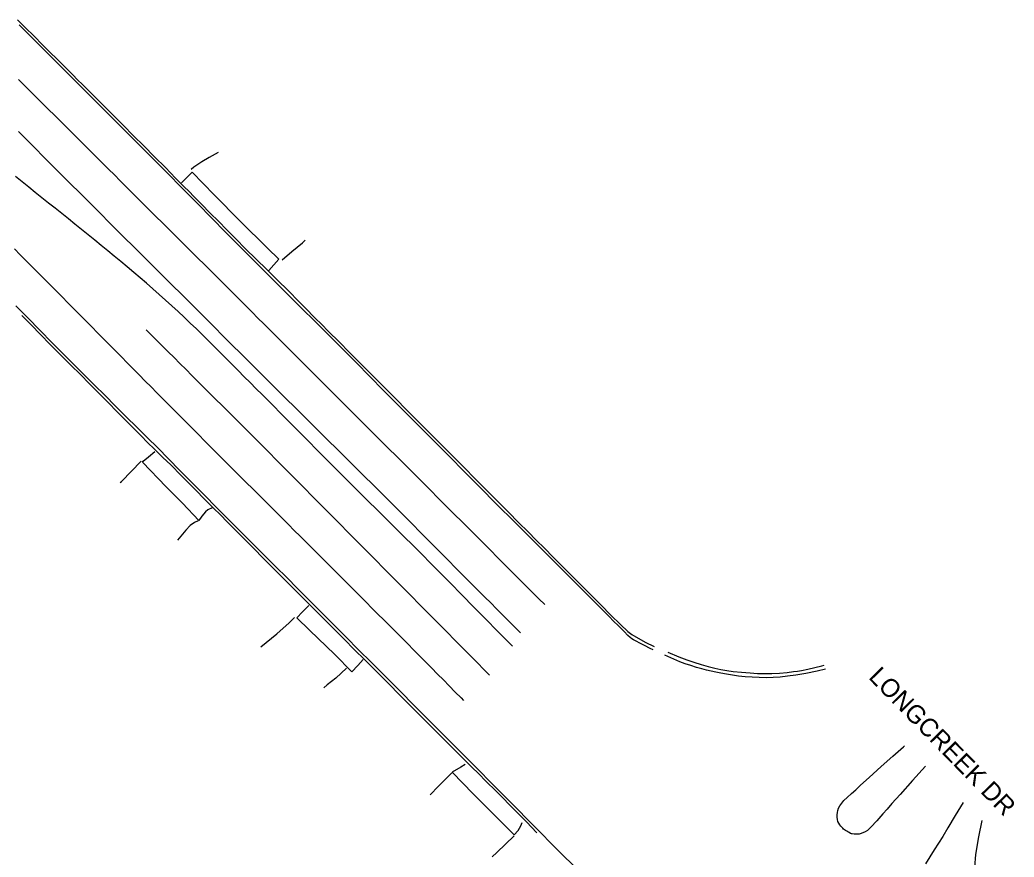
# Model space of a CAD drawing. Extents: x 1970211 to 1973046, y 801032 to 804001.
# Drawn here: x 1972255 to 1972549.2, y 801847.3 to 802095.2 of the extents above; entities that cross this region are included whole.
import ezdxf

# ---------------------------------------------------------------- set-up
doc = ezdxf.new("R2010")
doc.units = 0
for name, color, linetype in [('RD_EX_Conc', 7, 'Continuous'), ('RD_EX_Road', 7, 'Continuous'), ('RD_EX_Road_Paint', 7, 'Continuous'), ('RD_TX_RoadID', 7, 'Continuous')]:
    doc.layers.add(name, color=color, linetype=linetype)

msp = doc.modelspace()

# ---------------------------------------------------------------- linework, layer by layer
at = {"layer": 'RD_EX_Conc'}
for points in [[(1972254.32, 802095.16), (1972256.6, 802092.88), (1972259.19, 802090.31), (1972261.74, 802087.79), (1972263.9, 802085.63), (1972266.02, 802083.5), (1972268.46, 802081.06), (1972270.66, 802078.85), (1972272.09, 802077.43), (1972273.54, 802076), (1972275.78, 802073.77), (1972278.68, 802070.88), (1972282.09, 802067.46), (1972285.56, 802063.97), (1972288.64, 802060.87), (1972291.64, 802057.86), (1972294.86, 802054.65), (1972298.08, 802051.41), (1972301.09, 802048.34), (1972303.53, 802045.84), (1972305.04, 802044.31), (1972306.48, 802042.86), (1972308.73, 802040.59), (1972311.31, 802037.98), (1972313.75, 802035.52), (1972316.22, 802033.02), (1972318.9, 802030.31), (1972321.8, 802027.41), (1972324.92, 802024.35), (1972328.11, 802021.23), (1972331.23, 802018.14), (1972334.37, 802015), (1972337.63, 802011.72), (1972340.26, 802009.05), (1972341.52, 802007.76), (1972342.46, 802006.8), (1972344.12, 802005.13), (1972346.43, 802002.82), (1972349.33, 801999.92), (1972352.66, 801996.57), (1972356.27, 801992.94), (1972359.79, 801989.4), (1972362.87, 801986.3), (1972365.99, 801983.17), (1972369.6, 801979.51), (1972373.26, 801975.82), (1972376.51, 801972.57), (1972379.65, 801969.43), (1972383.01, 801966.07), (1972386.42, 801962.63), (1972389.74, 801959.28), (1972393.02, 801955.97), (1972396.31, 801952.67), (1972399.52, 801949.45), (1972402.57, 801946.38), (1972405.36, 801943.56), (1972407.8, 801941.11), (1972410.17, 801938.73), (1972412.77, 801936.14), (1972415.55, 801933.37), (1972418.45, 801930.46), (1972421.34, 801927.55), (1972424.08, 801924.78), (1972426.85, 801921.95), (1972429.87, 801918.91), (1972432.69, 801916.13), (1972434.85, 801914.12), (1972436.03, 801913.23), (1972439.99, 801910.96), (1972442.69, 801909.63)], [(1972302.78, 802046.9), (1972304.18, 802048.29), (1972305.95, 802050.06), (1972312.46, 802043.38), (1972320.22, 802035.57), (1972328.25, 802027.61), (1972331.62, 802024.32), (1972330.13, 802022.65), (1972328.69, 802020.93)], [(1972407.96, 801854.5), (1972404.88, 801857.7), (1972402.22, 801860.41), (1972399.91, 801862.74), (1972397.88, 801864.81), (1972395.74, 801866.99), (1972393.1, 801869.63), (1972390.59, 801872.12), (1972388.85, 801873.84), (1972387.03, 801875.64), (1972384.25, 801878.41), (1972381.02, 801881.63), (1972377.83, 801884.81), (1972374.62, 801888.03), (1972371.29, 801891.37), (1972367.7, 801894.98), (1972363.72, 801899.02), (1972359.93, 801902.84), (1972356.93, 801905.81), (1972354.09, 801908.61), (1972350.8, 801911.9), (1972347.39, 801915.33), (1972344.22, 801918.51), (1972341.37, 801921.38), (1972338.92, 801923.85), (1972336.57, 801926.23), (1972333.99, 801928.81), (1972331.01, 801931.79), (1972327.48, 801935.33), (1972323.68, 801939.16), (1972319.89, 801942.97), (1972316.55, 801946.33), (1972314.11, 801948.78), (1972312.47, 801950.44), (1972311.52, 801951.38), (1972310, 801952.92), (1972306.63, 801956.35), (1972302.73, 801960.3), (1972299.62, 801963.39), (1972297.34, 801965.62), (1972295.96, 801966.96), (1972294.72, 801968.15), (1972292.89, 801969.97), (1972290.75, 801972.12), (1972288.58, 801974.3), (1972286.29, 801976.62), (1972283.78, 801979.15), (1972281.12, 801981.84), (1972278.35, 801984.63), (1972275.58, 801987.43), (1972272.89, 801990.13), (1972270.11, 801992.91), (1972267.04, 801995.99), (1972263.96, 801999.1), (1972261.11, 802001.99), (1972258.33, 802004.83), (1972255.58, 802007.64)], [(1972311.92, 801950.74), (1972310.6, 801950.15), (1972309.94, 801949.49), (1972308.86, 801948.21), (1972307.98, 801946.95), (1972303.1, 801952.04), (1972298.28, 801956.95), (1972291.3, 801964.26), (1972291.47, 801964.47), (1972293.08, 801965.78), (1972294.91, 801967.37)], [(1972284.69, 801958.16), (1972285.05, 801958.52), (1972290.9, 801964.47)], [(1972307.75, 801946.81), (1972306.66, 801946.33), (1972305.37, 801945.43), (1972304.08, 801944.05), (1972302.15, 801941.76), (1972301.61, 801941.11)], [(1972340.52, 801921.81), (1972338.62, 801919.95), (1972336.93, 801918.13), (1972340.71, 801914.52), (1972348.19, 801907.27), (1972353.23, 801902.2), (1972354.95, 801904.04), (1972356.61, 801905.76)], [(1972446.68, 801907.93), (1972449.97, 801906.62), (1972452.36, 801905.73), (1972454.37, 801905.05), (1972456.54, 801904.36), (1972458.68, 801903.73), (1972460.61, 801903.25), (1972462.4, 801902.86), (1972464.12, 801902.53), (1972466.06, 801902.25), (1972468.53, 801902.01), (1972471.06, 801901.82), (1972473.21, 801901.68), (1972475.24, 801901.62), (1972477.44, 801901.65), (1972479.72, 801901.77), (1972481.97, 801901.99), (1972483.88, 801902.22), (1972485.1, 801902.37), (1972486.3, 801902.57), (1972488.14, 801902.96), (1972490.24, 801903.45), (1972492.25, 801903.94), (1972492.99, 801904.14)], [(1972522.93, 801874.23), (1972519.08, 801869.96), (1972515.41, 801865.86), (1972512.99, 801863.14), (1972511.57, 801861.53), (1972510.34, 801860.13), (1972508.51, 801858.06), (1972506.76, 801856.14), (1972505.77, 801855.2), (1972505.12, 801854.79), (1972504.4, 801854.45), (1972503.65, 801854.21), (1972503.27, 801854.14), (1972502.54, 801854.09), (1972501.87, 801854.11), (1972501.28, 801854.18), (1972501.01, 801854.24), (1972500.76, 801854.33), (1972500.31, 801854.55), (1972499.93, 801854.75), (1972499.62, 801854.95), (1972499.31, 801855.14), (1972499.01, 801855.36), (1972498.73, 801855.61), (1972498.47, 801855.89), (1972498.2, 801856.18), (1972497.91, 801856.49), (1972497.6, 801856.86), (1972497.29, 801857.31), (1972497.04, 801857.84), (1972496.87, 801858.44), (1972496.79, 801859.11), (1972496.81, 801859.83), (1972496.87, 801860.5), (1972496.99, 801861.12), (1972497.24, 801861.79), (1972497.63, 801862.52), (1972498.15, 801863.26), (1972498.82, 801864.02), (1972499.78, 801864.96), (1972501.01, 801866.09), (1972502.3, 801867.25), (1972503.75, 801868.56), (1972506.29, 801870.89), (1972509.87, 801874.17), (1972513.24, 801877.2), (1972516.4, 801879.95), (1972516.7, 801880.21)], [(1972386.7, 801874.68), (1972385.44, 801873.88), (1972382.93, 801872.47), (1972389.13, 801866.07), (1972395.53, 801859.62), (1972401.21, 801853.87), (1972402.41, 801855.22), (1972403.26, 801856.58), (1972403.65, 801857.5)], [(1972534.13, 801863.47), (1972531.74, 801859.58), (1972529.54, 801855.94), (1972528.04, 801853.44), (1972526.83, 801851.47), (1972525.53, 801849.43), (1972524.2, 801847.35), (1972522.9, 801845.28)], [(1972537.5, 801844.34), (1972537.81, 801848.1), (1972538.69, 801853.33), (1972539.71, 801858.11)]]:
    msp.add_lwpolyline(points, dxfattribs=at)
at = {"layer": 'RD_EX_Road'}
for points in [[(1972442.36, 801908.62), (1972441.44, 801909.09), (1972439.8, 801909.92), (1972438.38, 801910.64), (1972437.34, 801911.19), (1972436.59, 801911.61), (1972436.1, 801911.93), (1972435.58, 801912.34), (1972434.92, 801912.93), (1972433.74, 801914.08), (1972432.08, 801915.75), (1972430.68, 801917.16), (1972429.33, 801918.52), (1972426.12, 801921.74), (1972421.05, 801926.82), (1972416.04, 801931.85), (1972411.33, 801936.57), (1972406.44, 801941.46), (1972401.33, 801946.55), (1972396.15, 801951.73), (1972391.01, 801956.9), (1972386.38, 801961.56), (1972382.29, 801965.67), (1972378.56, 801969.45), (1972375.04, 801973.01), (1972371.21, 801976.86), (1972367.02, 801981.04), (1972362.73, 801985.35), (1972358.46, 801989.67), (1972354.58, 801993.59), (1972351.03, 801997.15), (1972347.07, 802001.11), (1972342.63, 802005.54), (1972338.03, 802010.13), (1972333.41, 802014.76), (1972329.28, 802018.88), (1972325.55, 802022.58), (1972321.14, 802027.01), (1972316.08, 802032.14), (1972311.61, 802036.68), (1972307.75, 802040.6), (1972303.31, 802045.08), (1972298.25, 802050.17), (1972293.45, 802054.99), (1972289.01, 802059.45), (1972284.66, 802063.79), (1972280.29, 802068.15), (1972275.53, 802072.92), (1972270.36, 802078.1), (1972265.12, 802083.35), (1972259.9, 802088.59), (1972254.78, 802093.69)], [(1972313.71, 802055.9), (1972310.99, 802054.42), (1972308.88, 802053.18), (1972306.51, 802051.51), (1972305.63, 802050.88)], [(1972332.63, 802024.16), (1972335.51, 802026.6), (1972338.6, 802029.18), (1972339.44, 802029.93)], [(1972418.75, 801844.81), (1972415.43, 801848.12), (1972412.22, 801851.35), (1972409.09, 801854.53), (1972405.59, 801858.08), (1972401.83, 801861.88), (1972398.97, 801864.77), (1972396.95, 801866.81), (1972394.26, 801869.53), (1972390.77, 801873.04), (1972387.29, 801876.54), (1972383.88, 801879.94), (1972380.22, 801883.63), (1972376.23, 801887.66), (1972371.89, 801892.02), (1972367.28, 801896.62), (1972362.97, 801900.92), (1972359.03, 801904.88), (1972355.22, 801908.71), (1972351.52, 801912.42), (1972347.98, 801915.97), (1972344.57, 801919.39), (1972340.99, 801923), (1972337.26, 801926.76), (1972333.89, 801930.14), (1972330.87, 801933.16), (1972327.7, 801936.31), (1972324.31, 801939.68), (1972320.75, 801943.23), (1972317.06, 801946.94), (1972313.32, 801950.71), (1972309.56, 801954.52), (1972305.89, 801958.21), (1972302.35, 801961.78), (1972298.98, 801965.18), (1972295.78, 801968.42), (1972292.66, 801971.53), (1972289.59, 801974.55), (1972286.46, 801977.64), (1972283.27, 801980.83), (1972280.09, 801984.01), (1972277.06, 801987.06), (1972274.93, 801989.2), (1972273.55, 801990.56), (1972271.32, 801992.78), (1972268.11, 801996.03), (1972264.6, 801999.59), (1972260.95, 802003.3), (1972257.32, 802006.96), (1972253.8, 802010.49)], [(1972326.32, 801909.54), (1972331.05, 801913.37), (1972334.69, 801916.61), (1972336.25, 801918.24)], [(1972493.32, 801902.9), (1972490.87, 801902.32), (1972487.52, 801901.66), (1972484.57, 801901.18), (1972482.13, 801900.86), (1972479.93, 801900.62), (1972477.91, 801900.45), (1972475.85, 801900.39), (1972473.75, 801900.44), (1972471.66, 801900.54), (1972469.58, 801900.68), (1972467.63, 801900.9), (1972465.8, 801901.17), (1972464.05, 801901.46), (1972462.4, 801901.75), (1972460.89, 801902.05), (1972459.51, 801902.36), (1972458.16, 801902.68), (1972456.79, 801903.03), (1972455.22, 801903.47), (1972453.49, 801903.99), (1972451.86, 801904.52), (1972450.21, 801905.13), (1972447.57, 801906.27), (1972445.81, 801907.06)], [(1972351.64, 801903.2), (1972350.05, 801901.76), (1972348.44, 801900.32), (1972345.94, 801898.28), (1972344.95, 801897.43)], [(1972376.37, 801865.77), (1972378.86, 801868.33), (1972382.79, 801872.25)], [(1972394.72, 801847.36), (1972396.07, 801848.65), (1972401.21, 801853.58)]]:
    msp.add_lwpolyline(points, dxfattribs=at)
at = {"layer": 'RD_EX_Road_Paint'}
for points in [[(1972410.31, 801922.04), (1972408.53, 801923.81), (1972406.76, 801925.57), (1972404.99, 801927.34), (1972403.22, 801929.1), (1972401.46, 801930.87), (1972399.69, 801932.64), (1972397.93, 801934.41), (1972396.16, 801936.18), (1972394.4, 801937.95), (1972392.63, 801939.72), (1972390.87, 801941.49), (1972389.1, 801943.27), (1972387.34, 801945.04), (1972385.57, 801946.81), (1972383.81, 801948.58), (1972382.04, 801950.35), (1972380.28, 801952.12), (1972378.51, 801953.89), (1972376.75, 801955.66), (1972374.98, 801957.43), (1972373.21, 801959.19), (1972371.44, 801960.96), (1972369.67, 801962.72), (1972367.9, 801964.49), (1972366.13, 801966.26), (1972364.36, 801968.02), (1972362.59, 801969.79), (1972360.82, 801971.55), (1972359.05, 801973.32), (1972357.28, 801975.08), (1972355.51, 801976.85), (1972353.74, 801978.61), (1972351.97, 801980.38), (1972350.2, 801982.14), (1972348.43, 801983.91), (1972346.66, 801985.68), (1972344.89, 801987.44), (1972343.12, 801989.21), (1972341.36, 801990.98), (1972339.59, 801992.75), (1972337.82, 801994.52), (1972336.06, 801996.29), (1972334.29, 801998.06), (1972332.52, 801999.82), (1972330.76, 802001.59), (1972328.99, 802003.36), (1972327.22, 802005.13), (1972325.45, 802006.9), (1972323.69, 802008.67), (1972321.92, 802010.44), (1972320.15, 802012.2), (1972318.39, 802013.97), (1972316.61, 802015.73), (1972314.84, 802017.5), (1972313.07, 802019.26), (1972311.3, 802021.02), (1972309.52, 802022.79), (1972307.75, 802024.55), (1972305.98, 802026.31), (1972304.21, 802028.08), (1972302.43, 802029.84), (1972300.66, 802031.6), (1972298.89, 802033.37), (1972297.12, 802035.13), (1972295.34, 802036.89), (1972293.57, 802038.65), (1972291.8, 802040.42), (1972290.03, 802042.18), (1972288.26, 802043.95), (1972286.49, 802045.71), (1972284.72, 802047.48), (1972282.95, 802049.24), (1972281.18, 802051.01), (1972279.41, 802052.77), (1972277.64, 802054.54), (1972275.87, 802056.31), (1972274.1, 802058.07), (1972272.33, 802059.84), (1972270.56, 802061.6), (1972268.79, 802063.37), (1972267.02, 802065.13), (1972265.25, 802066.9), (1972263.48, 802068.67), (1972261.71, 802070.43), (1972259.94, 802072.2), (1972258.17, 802073.96), (1972256.4, 802075.73), (1972254.63, 802077.49)], [(1972403.12, 801913.68), (1972401.36, 801915.45), (1972399.59, 801917.22), (1972397.83, 801918.99), (1972396.06, 801920.76), (1972394.3, 801922.53), (1972392.53, 801924.3), (1972390.77, 801926.08), (1972389.01, 801927.85), (1972387.25, 801929.63), (1972385.49, 801931.4), (1972383.73, 801933.18), (1972381.98, 801934.96), (1972380.22, 801936.73), (1972378.46, 801938.51), (1972376.7, 801940.28), (1972374.94, 801942.06), (1972373.18, 801943.84), (1972371.42, 801945.61), (1972369.66, 801947.39), (1972367.88, 801949.15), (1972366.11, 801950.91), (1972364.34, 801952.67), (1972362.56, 801954.43), (1972360.79, 801956.2), (1972359.02, 801957.96), (1972357.24, 801959.72), (1972355.47, 801961.48), (1972353.69, 801963.24), (1972351.92, 801965.01), (1972350.15, 801966.77), (1972348.37, 801968.53), (1972346.6, 801970.29), (1972344.83, 801972.05), (1972343.05, 801973.81), (1972341.28, 801975.58), (1972339.5, 801977.34), (1972337.73, 801979.1), (1972335.96, 801980.86), (1972334.18, 801982.62), (1972332.41, 801984.39), (1972330.64, 801986.15), (1972328.87, 801987.92), (1972327.1, 801989.68), (1972325.33, 801991.44), (1972323.56, 801993.21), (1972321.78, 801994.97), (1972320.01, 801996.74), (1972318.24, 801998.5), (1972316.47, 802000.26), (1972314.7, 802002.03), (1972312.93, 802003.8), (1972311.17, 802005.57), (1972309.4, 802007.34), (1972307.63, 802009.1), (1972305.86, 802010.87), (1972304.1, 802012.64), (1972302.33, 802014.41), (1972300.56, 802016.17), (1972298.79, 802017.94), (1972297.01, 802019.7), (1972295.24, 802021.46), (1972293.47, 802023.23), (1972291.7, 802024.99), (1972289.93, 802026.75), (1972288.15, 802028.52), (1972286.38, 802030.28), (1972284.61, 802032.05), (1972282.84, 802033.81), (1972281.07, 802035.58), (1972279.3, 802037.34), (1972277.53, 802039.11), (1972275.76, 802040.87), (1972273.99, 802042.64), (1972272.22, 802044.4), (1972270.46, 802046.17), (1972268.69, 802047.95), (1972266.93, 802049.72), (1972265.17, 802051.49), (1972263.4, 802053.26), (1972261.64, 802055.03), (1972259.87, 802056.81), (1972258.11, 802058.58), (1972256.35, 802060.35), (1972254.58, 802062.11)], [(1972400.73, 801909.78), (1972398.97, 801911.56), (1972397.22, 801913.34), (1972395.46, 801915.12), (1972393.7, 801916.9), (1972391.95, 801918.67), (1972390.19, 801920.45), (1972388.43, 801922.23), (1972386.67, 801924.01), (1972384.92, 801925.79), (1972383.16, 801927.57), (1972381.4, 801929.34), (1972379.64, 801931.12), (1972377.89, 801932.9), (1972376.13, 801934.68), (1972374.37, 801936.46), (1972372.62, 801938.24), (1972370.85, 801940), (1972369.07, 801941.76), (1972367.29, 801943.52), (1972365.52, 801945.28), (1972363.74, 801947.04), (1972361.97, 801948.8), (1972360.19, 801950.56), (1972358.41, 801952.32), (1972356.64, 801954.08), (1972354.86, 801955.83), (1972353.08, 801957.59), (1972351.31, 801959.35), (1972349.54, 801961.12), (1972347.78, 801962.9), (1972346.02, 801964.68), (1972344.26, 801966.45), (1972342.51, 801968.23), (1972340.75, 801970), (1972338.99, 801971.78), (1972337.23, 801973.55), (1972335.47, 801975.33), (1972333.71, 801977.11), (1972331.95, 801978.88), (1972330.19, 801980.66), (1972328.43, 801982.43), (1972326.66, 801984.21), (1972324.9, 801985.98), (1972323.14, 801987.76), (1972321.38, 801989.53), (1972319.62, 801991.31), (1972317.86, 801993.08), (1972316.1, 801994.86), (1972314.34, 801996.63), (1972312.58, 801998.41), (1972310.8, 802000.16), (1972309.01, 802001.91), (1972307.22, 802003.66), (1972305.41, 802005.38), (1972303.6, 802007.1), (1972301.79, 802008.82), (1972299.95, 802010.51), (1972298.09, 802012.18), (1972296.23, 802013.86), (1972294.37, 802015.53), (1972292.49, 802017.18), (1972290.58, 802018.79), (1972288.68, 802020.41), (1972286.77, 802022.02), (1972284.86, 802023.63), (1972282.92, 802025.22), (1972280.99, 802026.81), (1972279.06, 802028.4), (1972277.13, 802029.99), (1972275.19, 802031.56), (1972273.24, 802033.13), (1972271.3, 802034.7), (1972269.35, 802036.27), (1972267.4, 802037.83), (1972265.43, 802039.38), (1972263.47, 802040.92), (1972261.51, 802042.47), (1972259.55, 802044.03), (1972257.61, 802045.6), (1972255.67, 802047.18), (1972253.73, 802048.76)], [(1972253.36, 802027.36), (1972255.13, 802025.59), (1972256.9, 802023.82), (1972258.67, 802022.06), (1972260.43, 802020.29), (1972262.2, 802018.52), (1972263.97, 802016.75), (1972265.72, 802014.97), (1972267.48, 802013.19), (1972269.23, 802011.41), (1972270.99, 802009.63), (1972272.74, 802007.85), (1972274.49, 802006.06), (1972276.25, 802004.28), (1972278, 802002.5), (1972279.75, 802000.72), (1972281.51, 801998.94), (1972283.26, 801997.16), (1972285.02, 801995.37), (1972286.77, 801993.59), (1972288.52, 801991.81), (1972290.28, 801990.03), (1972292.03, 801988.25), (1972293.8, 801986.48), (1972295.56, 801984.71), (1972297.32, 801982.94), (1972299.09, 801981.16), (1972300.85, 801979.39), (1972302.62, 801977.62), (1972304.38, 801975.85), (1972306.15, 801974.08), (1972307.91, 801972.31), (1972309.67, 801970.54), (1972311.44, 801968.76), (1972313.2, 801966.99), (1972314.97, 801965.22), (1972316.73, 801963.45), (1972318.49, 801961.68), (1972320.26, 801959.91), (1972322.03, 801958.15), (1972323.8, 801956.38), (1972325.57, 801954.62), (1972327.35, 801952.85), (1972329.12, 801951.09), (1972330.89, 801949.32), (1972332.66, 801947.56), (1972334.43, 801945.8), (1972336.2, 801944.03), (1972337.97, 801942.27), (1972339.75, 801940.5), (1972341.52, 801938.74), (1972343.29, 801936.98), (1972345.06, 801935.21), (1972346.83, 801933.45), (1972348.6, 801931.68), (1972350.36, 801929.91), (1972352.13, 801928.14), (1972353.89, 801926.36), (1972355.65, 801924.59), (1972357.41, 801922.82), (1972359.18, 801921.04), (1972360.94, 801919.27), (1972362.7, 801917.5), (1972364.46, 801915.73), (1972366.23, 801913.95), (1972367.99, 801912.18), (1972369.74, 801910.4), (1972371.5, 801908.62), (1972373.26, 801906.85), (1972375.02, 801905.07), (1972376.78, 801903.29), (1972378.54, 801901.51), (1972380.3, 801899.74), (1972382.05, 801897.96), (1972383.81, 801896.18), (1972385.57, 801894.41), (1972386.29, 801893.68)], [(1972393.97, 801901.16), (1972392.21, 801902.93), (1972390.45, 801904.71), (1972388.7, 801906.49), (1972386.94, 801908.27), (1972385.18, 801910.04), (1972383.42, 801911.82), (1972381.67, 801913.6), (1972379.91, 801915.38), (1972378.15, 801917.16), (1972376.39, 801918.93), (1972374.64, 801920.71), (1972372.88, 801922.49), (1972371.12, 801924.27), (1972369.36, 801926.04), (1972367.61, 801927.82), (1972365.85, 801929.6), (1972364.09, 801931.38), (1972362.33, 801933.15), (1972360.57, 801934.93), (1972358.81, 801936.71), (1972357.05, 801938.48), (1972355.29, 801940.26), (1972353.53, 801942.04), (1972351.77, 801943.81), (1972350.02, 801945.59), (1972348.26, 801947.36), (1972346.5, 801949.14), (1972344.74, 801950.92), (1972342.98, 801952.69), (1972341.22, 801954.47), (1972339.46, 801956.25), (1972337.7, 801958.02), (1972335.94, 801959.8), (1972334.18, 801961.57), (1972332.42, 801963.35), (1972330.66, 801965.13), (1972328.91, 801966.9), (1972327.15, 801968.68), (1972325.39, 801970.46), (1972323.63, 801972.23), (1972321.86, 801974), (1972320.09, 801975.76), (1972318.31, 801977.53), (1972316.54, 801979.29), (1972314.77, 801981.05), (1972313, 801982.82), (1972311.23, 801984.58), (1972309.46, 801986.35), (1972307.69, 801988.11), (1972305.92, 801989.88), (1972304.15, 801991.64), (1972302.37, 801993.41), (1972300.6, 801995.17), (1972298.83, 801996.93), (1972297.06, 801998.7), (1972295.29, 802000.46), (1972293.52, 802002.23), (1972292.38, 802003.37)]]:
    msp.add_lwpolyline(points, dxfattribs=at)

# ---------------------------------------------------------------- texts
at = {"layer": 'RD_TX_RoadID'}
msp.add_text('LONGCREEK DR', height=5.4, rotation=314.4101, dxfattribs=at).set_placement((1972505.83, 801900.36))

doc.saveas('drawing.dxf')
